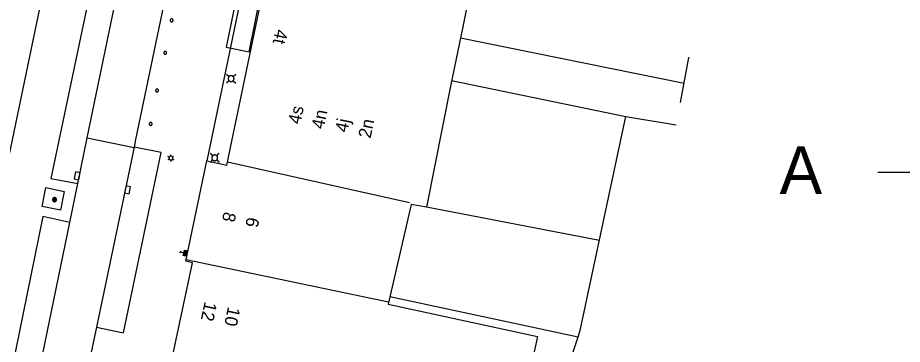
# Model space of a CAD drawing. Extents: x 81065 to 81486, y 452384 to 452681.
# Drawn here: x 81276.3 to 81331.8, y 452560.2 to 452580.7 of the extents above; entities that cross this region are included whole.
import ezdxf

# ---------------------------------------------------------------- set-up
doc = ezdxf.new("R2010")
doc.units = 0
for name, color, linetype in [('B-BH-AL-TOPOGRAFIE_HUISNUMMER-T25', 7, 'Continuous'), ('B-BH-GR-BOOM-S', 7, 'Continuous'), ('B-BH-IE-MEUBILAIR_WEGMEUBILAIR_LICHTMAST-S', 7, 'Continuous'), ('B-BH-IE-MEUBILAIR_WEGMEUBILAIR_PAAL-S', 7, 'Continuous'), ('B-BH-KL-DATA_CAI_KAST-S', 7, 'Continuous'), ('B-BH-OG-TERREIN_ERF-GV', 7, 'Continuous'), ('B-BH-OG-TOPOGRAFIE_BEBOUWING-GV', 7, 'Continuous'), ('B-BH-OG-TOPOGRAFIE_BEBOUWING_PANDSCHEIDING-GV', 7, 'Continuous'), ('B-BH-VH-KANTOPSLUITING-GV', 7, 'Continuous'), ('B-SRI-KOLK_COMBINATIE-S', 7, 'Continuous'), ('X-XX-AL-TEKENBLAD_KADER-G', 7, 'Continuous')]:
    doc.layers.add(name, color=color, linetype=linetype)

msp = doc.modelspace()

# ---------------------------------------------------------------- linework, layer by layer
at = {"layer": 'B-BH-GR-BOOM-S'}
for points in [[(81278.456, 452569.271), (81278.457, 452569.257), (81278.459, 452569.244), (81278.462, 452569.231), (81278.467, 452569.219), (81278.473, 452569.207), (81278.481, 452569.195), (81278.489, 452569.185), (81278.499, 452569.175), (81278.509, 452569.167), (81278.521, 452569.159), (81278.533, 452569.153), (81278.545, 452569.148), (81278.558, 452569.145), (81278.571, 452569.143), (81278.585, 452569.142), (81278.598, 452569.143), (81278.612, 452569.145), (81278.625, 452569.148), (81278.637, 452569.153), (81278.649, 452569.159), (81278.661, 452569.167), (81278.671, 452569.175), (81278.681, 452569.185), (81278.689, 452569.195), (81278.697, 452569.207), (81278.703, 452569.219), (81278.707, 452569.231), (81278.711, 452569.244), (81278.713, 452569.257), (81278.714, 452569.271), (81278.713, 452569.284), (81278.711, 452569.298), (81278.707, 452569.311), (81278.703, 452569.323), (81278.697, 452569.335), (81278.689, 452569.347), (81278.681, 452569.357), (81278.671, 452569.367), (81278.661, 452569.375), (81278.649, 452569.383), (81278.637, 452569.389), (81278.625, 452569.393), (81278.612, 452569.397), (81278.598, 452569.399), (81278.585, 452569.4), (81278.571, 452569.399), (81278.558, 452569.397), (81278.545, 452569.393), (81278.533, 452569.389), (81278.521, 452569.383), (81278.509, 452569.375), (81278.499, 452569.367), (81278.489, 452569.357), (81278.481, 452569.347), (81278.473, 452569.335), (81278.467, 452569.323), (81278.462, 452569.311), (81278.459, 452569.298), (81278.457, 452569.284), (81278.456, 452569.271)], [(81278.481, 452569.271), (81278.481, 452569.26), (81278.483, 452569.249), (81278.486, 452569.239), (81278.49, 452569.228), (81278.494, 452569.219), (81278.5, 452569.21), (81278.507, 452569.201), (81278.515, 452569.193), (81278.524, 452569.186), (81278.533, 452569.18), (81278.542, 452569.176), (81278.553, 452569.172), (81278.563, 452569.169), (81278.574, 452569.167), (81278.585, 452569.167), (81278.596, 452569.167), (81278.607, 452569.169), (81278.617, 452569.172), (81278.627, 452569.176), (81278.637, 452569.18), (81278.646, 452569.186), (81278.655, 452569.193), (81278.663, 452569.201), (81278.669, 452569.21), (81278.675, 452569.219), (81278.68, 452569.228), (81278.684, 452569.239), (81278.687, 452569.249), (81278.689, 452569.26), (81278.689, 452569.271), (81278.689, 452569.282), (81278.687, 452569.293), (81278.684, 452569.303), (81278.68, 452569.313), (81278.675, 452569.323), (81278.669, 452569.332), (81278.663, 452569.341), (81278.655, 452569.349), (81278.646, 452569.355), (81278.637, 452569.361), (81278.627, 452569.366), (81278.617, 452569.37), (81278.607, 452569.373), (81278.596, 452569.375), (81278.585, 452569.375), (81278.574, 452569.375), (81278.563, 452569.373), (81278.553, 452569.37), (81278.542, 452569.366), (81278.533, 452569.361), (81278.524, 452569.355), (81278.515, 452569.349), (81278.507, 452569.341), (81278.5, 452569.332), (81278.494, 452569.323), (81278.49, 452569.313), (81278.486, 452569.303), (81278.483, 452569.293), (81278.481, 452569.282), (81278.481, 452569.271)], [(81278.503, 452569.271), (81278.504, 452569.262), (81278.505, 452569.254), (81278.507, 452569.246), (81278.51, 452569.238), (81278.514, 452569.23), (81278.519, 452569.223), (81278.524, 452569.216), (81278.53, 452569.21), (81278.537, 452569.205), (81278.544, 452569.2), (81278.552, 452569.196), (81278.56, 452569.193), (81278.568, 452569.191), (81278.576, 452569.19), (81278.585, 452569.189), (81278.593, 452569.19), (81278.602, 452569.191), (81278.61, 452569.193), (81278.618, 452569.196), (81278.626, 452569.2), (81278.633, 452569.205), (81278.64, 452569.21), (81278.646, 452569.216), (81278.651, 452569.223), (81278.656, 452569.23), (81278.659, 452569.238), (81278.663, 452569.246), (81278.665, 452569.254), (81278.666, 452569.262), (81278.667, 452569.271), (81278.666, 452569.279), (81278.665, 452569.288), (81278.663, 452569.296), (81278.659, 452569.304), (81278.656, 452569.312), (81278.651, 452569.319), (81278.646, 452569.326), (81278.64, 452569.332), (81278.633, 452569.337), (81278.626, 452569.342), (81278.618, 452569.345), (81278.61, 452569.349), (81278.602, 452569.351), (81278.593, 452569.352), (81278.585, 452569.353), (81278.576, 452569.352), (81278.568, 452569.351), (81278.56, 452569.349), (81278.552, 452569.345), (81278.544, 452569.342), (81278.537, 452569.337), (81278.53, 452569.332), (81278.524, 452569.326), (81278.519, 452569.319), (81278.514, 452569.312), (81278.51, 452569.304), (81278.507, 452569.296), (81278.505, 452569.288), (81278.504, 452569.279), (81278.503, 452569.271)], [(81278.526, 452569.271), (81278.527, 452569.265), (81278.528, 452569.259), (81278.529, 452569.253), (81278.531, 452569.247), (81278.534, 452569.242), (81278.538, 452569.236), (81278.541, 452569.232), (81278.546, 452569.227), (81278.55, 452569.224), (81278.556, 452569.22), (81278.561, 452569.217), (81278.567, 452569.215), (81278.573, 452569.214), (81278.579, 452569.213), (81278.585, 452569.212), (81278.591, 452569.213), (81278.597, 452569.214), (81278.603, 452569.215), (81278.609, 452569.217), (81278.614, 452569.22), (81278.619, 452569.224), (81278.624, 452569.227), (81278.629, 452569.232), (81278.632, 452569.236), (81278.636, 452569.242), (81278.639, 452569.247), (81278.641, 452569.253), (81278.642, 452569.259), (81278.643, 452569.265), (81278.644, 452569.271), (81278.643, 452569.277), (81278.642, 452569.283), (81278.641, 452569.289), (81278.639, 452569.295), (81278.636, 452569.3), (81278.632, 452569.305), (81278.629, 452569.31), (81278.624, 452569.315), (81278.619, 452569.318), (81278.614, 452569.322), (81278.609, 452569.325), (81278.603, 452569.327), (81278.597, 452569.328), (81278.591, 452569.329), (81278.585, 452569.33), (81278.579, 452569.329), (81278.573, 452569.328), (81278.567, 452569.327), (81278.561, 452569.325), (81278.556, 452569.322), (81278.55, 452569.318), (81278.546, 452569.315), (81278.541, 452569.31), (81278.538, 452569.305), (81278.534, 452569.3), (81278.531, 452569.295), (81278.529, 452569.289), (81278.528, 452569.283), (81278.527, 452569.277), (81278.526, 452569.271)], [(81278.549, 452569.271), (81278.549, 452569.267), (81278.55, 452569.264), (81278.551, 452569.26), (81278.552, 452569.256), (81278.554, 452569.253), (81278.556, 452569.25), (81278.558, 452569.247), (81278.561, 452569.244), (81278.564, 452569.242), (81278.567, 452569.24), (81278.57, 452569.238), (81278.574, 452569.237), (81278.578, 452569.236), (81278.581, 452569.235), (81278.585, 452569.235), (81278.589, 452569.235), (81278.592, 452569.236), (81278.596, 452569.237), (81278.6, 452569.238), (81278.603, 452569.24), (81278.606, 452569.242), (81278.609, 452569.244), (81278.611, 452569.247), (81278.614, 452569.25), (81278.616, 452569.253), (81278.618, 452569.256), (81278.619, 452569.26), (81278.62, 452569.264), (81278.621, 452569.267), (81278.621, 452569.271), (81278.621, 452569.275), (81278.62, 452569.278), (81278.619, 452569.282), (81278.618, 452569.286), (81278.616, 452569.289), (81278.614, 452569.292), (81278.611, 452569.295), (81278.609, 452569.297), (81278.606, 452569.3), (81278.603, 452569.302), (81278.6, 452569.304), (81278.596, 452569.305), (81278.592, 452569.306), (81278.589, 452569.307), (81278.585, 452569.307), (81278.581, 452569.307), (81278.578, 452569.306), (81278.574, 452569.305), (81278.57, 452569.304), (81278.567, 452569.302), (81278.564, 452569.3), (81278.561, 452569.297), (81278.558, 452569.295), (81278.556, 452569.292), (81278.554, 452569.289), (81278.552, 452569.286), (81278.551, 452569.282), (81278.55, 452569.278), (81278.549, 452569.275), (81278.549, 452569.271)], [(81278.572, 452569.271), (81278.572, 452569.27), (81278.572, 452569.268), (81278.573, 452569.267), (81278.573, 452569.266), (81278.574, 452569.265), (81278.575, 452569.263), (81278.575, 452569.262), (81278.576, 452569.261), (81278.577, 452569.261), (81278.579, 452569.26), (81278.58, 452569.259), (81278.581, 452569.259), (81278.582, 452569.258), (81278.584, 452569.258), (81278.585, 452569.258), (81278.586, 452569.258), (81278.588, 452569.258), (81278.589, 452569.259), (81278.59, 452569.259), (81278.591, 452569.26), (81278.593, 452569.261), (81278.594, 452569.261), (81278.595, 452569.262), (81278.595, 452569.263), (81278.596, 452569.265), (81278.597, 452569.266), (81278.597, 452569.267), (81278.598, 452569.268), (81278.598, 452569.27), (81278.598, 452569.271), (81278.598, 452569.272), (81278.598, 452569.274), (81278.597, 452569.275), (81278.597, 452569.276), (81278.596, 452569.277), (81278.595, 452569.279), (81278.595, 452569.28), (81278.594, 452569.281), (81278.593, 452569.281), (81278.591, 452569.282), (81278.59, 452569.283), (81278.589, 452569.283), (81278.588, 452569.284), (81278.586, 452569.284), (81278.585, 452569.284), (81278.584, 452569.284), (81278.582, 452569.284), (81278.581, 452569.283), (81278.58, 452569.283), (81278.579, 452569.282), (81278.577, 452569.281), (81278.576, 452569.281), (81278.575, 452569.28), (81278.575, 452569.279), (81278.574, 452569.277), (81278.573, 452569.276), (81278.573, 452569.275), (81278.572, 452569.274), (81278.572, 452569.272), (81278.572, 452569.271)]]:
    msp.add_lwpolyline(points, dxfattribs=at)
at = {"layer": 'B-BH-IE-MEUBILAIR_WEGMEUBILAIR_LICHTMAST-S'}
for p, q in [((81285.787, 452571.941), (81285.708, 452571.987)), ((81285.787, 452571.819), (81285.708, 452571.773)), ((81285.893, 452572.002), (81285.893, 452572.094)), ((81285.998, 452571.941), (81286.078, 452571.987)), ((81285.998, 452571.819), (81286.078, 452571.773)), ((81285.893, 452571.758), (81285.893, 452571.666))]:
    msp.add_line(p, q, dxfattribs=at)
msp.add_lwpolyline([(81285.771, 452571.88), (81285.772, 452571.867), (81285.773, 452571.854), (81285.777, 452571.842), (81285.781, 452571.83), (81285.787, 452571.819), (81285.794, 452571.808), (81285.802, 452571.798), (81285.811, 452571.789), (81285.821, 452571.781), (81285.832, 452571.774), (81285.843, 452571.768), (81285.855, 452571.764), (81285.868, 452571.76), (81285.88, 452571.759), (81285.893, 452571.758), (81285.906, 452571.759), (81285.918, 452571.76), (81285.931, 452571.764), (81285.943, 452571.768), (81285.954, 452571.774), (81285.965, 452571.781), (81285.975, 452571.789), (81285.984, 452571.798), (81285.992, 452571.808), (81285.999, 452571.819), (81286.004, 452571.83), (81286.009, 452571.842), (81286.012, 452571.854), (81286.014, 452571.867), (81286.015, 452571.88), (81286.014, 452571.893), (81286.012, 452571.905), (81286.009, 452571.918), (81286.004, 452571.93), (81285.999, 452571.941), (81285.992, 452571.952), (81285.984, 452571.962), (81285.975, 452571.971), (81285.965, 452571.979), (81285.954, 452571.986), (81285.943, 452571.991), (81285.931, 452571.996), (81285.918, 452571.999), (81285.906, 452572.001), (81285.893, 452572.002), (81285.88, 452572.001), (81285.867, 452571.999), (81285.855, 452571.996), (81285.843, 452571.991), (81285.832, 452571.986), (81285.821, 452571.979), (81285.811, 452571.971), (81285.802, 452571.962), (81285.794, 452571.952), (81285.787, 452571.941), (81285.781, 452571.93), (81285.777, 452571.918), (81285.773, 452571.905), (81285.772, 452571.893), (81285.771, 452571.88)], dxfattribs=at)
at = {"layer": 'B-BH-IE-MEUBILAIR_WEGMEUBILAIR_PAAL-S'}
for points in [[(81285.846, 452580.529), (81285.847, 452580.519), (81285.848, 452580.51), (81285.851, 452580.5), (81285.854, 452580.491), (81285.858, 452580.483), (81285.864, 452580.475), (81285.87, 452580.467), (81285.876, 452580.461), (81285.884, 452580.455), (81285.892, 452580.449), (81285.901, 452580.445), (81285.909, 452580.442), (81285.919, 452580.439), (81285.928, 452580.438), (81285.938, 452580.437), (81285.947, 452580.438), (81285.957, 452580.439), (81285.966, 452580.442), (81285.975, 452580.445), (81285.984, 452580.449), (81285.992, 452580.455), (81285.999, 452580.461), (81286.006, 452580.467), (81286.012, 452580.475), (81286.017, 452580.483), (81286.021, 452580.491), (81286.025, 452580.5), (81286.027, 452580.51), (81286.029, 452580.519), (81286.029, 452580.529), (81286.029, 452580.538), (81286.027, 452580.548), (81286.025, 452580.557), (81286.021, 452580.566), (81286.017, 452580.574), (81286.012, 452580.582), (81286.006, 452580.59), (81285.999, 452580.597), (81285.992, 452580.603), (81285.984, 452580.608), (81285.975, 452580.612), (81285.966, 452580.616), (81285.957, 452580.618), (81285.947, 452580.62), (81285.938, 452580.62), (81285.928, 452580.62), (81285.919, 452580.618), (81285.909, 452580.616), (81285.901, 452580.612), (81285.892, 452580.608), (81285.884, 452580.603), (81285.876, 452580.597), (81285.87, 452580.59), (81285.864, 452580.582), (81285.858, 452580.574), (81285.854, 452580.566), (81285.851, 452580.557), (81285.848, 452580.548), (81285.847, 452580.538), (81285.846, 452580.529)], [(81285.442, 452578.492), (81285.443, 452578.482), (81285.444, 452578.473), (81285.447, 452578.463), (81285.45, 452578.454), (81285.454, 452578.446), (81285.46, 452578.438), (81285.466, 452578.43), (81285.472, 452578.424), (81285.48, 452578.418), (81285.488, 452578.412), (81285.497, 452578.408), (81285.505, 452578.405), (81285.515, 452578.402), (81285.524, 452578.401), (81285.534, 452578.4), (81285.543, 452578.401), (81285.553, 452578.402), (81285.562, 452578.405), (81285.571, 452578.408), (81285.58, 452578.412), (81285.588, 452578.418), (81285.595, 452578.424), (81285.602, 452578.43), (81285.608, 452578.438), (81285.613, 452578.446), (81285.617, 452578.454), (81285.621, 452578.463), (81285.623, 452578.473), (81285.625, 452578.482), (81285.625, 452578.492), (81285.625, 452578.501), (81285.623, 452578.511), (81285.621, 452578.52), (81285.617, 452578.529), (81285.613, 452578.537), (81285.608, 452578.545), (81285.602, 452578.553), (81285.595, 452578.56), (81285.588, 452578.566), (81285.58, 452578.571), (81285.571, 452578.575), (81285.562, 452578.579), (81285.553, 452578.581), (81285.543, 452578.583), (81285.534, 452578.583), (81285.524, 452578.583), (81285.515, 452578.581), (81285.505, 452578.579), (81285.497, 452578.575), (81285.488, 452578.571), (81285.48, 452578.566), (81285.472, 452578.56), (81285.466, 452578.553), (81285.46, 452578.545), (81285.454, 452578.537), (81285.45, 452578.529), (81285.447, 452578.52), (81285.444, 452578.511), (81285.443, 452578.501), (81285.442, 452578.492)], [(81284.931, 452576.122), (81284.932, 452576.112), (81284.933, 452576.103), (81284.936, 452576.093), (81284.939, 452576.084), (81284.943, 452576.076), (81284.949, 452576.068), (81284.955, 452576.06), (81284.961, 452576.054), (81284.969, 452576.048), (81284.977, 452576.042), (81284.986, 452576.038), (81284.994, 452576.035), (81285.004, 452576.032), (81285.013, 452576.031), (81285.023, 452576.03), (81285.032, 452576.031), (81285.042, 452576.032), (81285.051, 452576.035), (81285.06, 452576.038), (81285.069, 452576.042), (81285.077, 452576.048), (81285.084, 452576.054), (81285.091, 452576.06), (81285.097, 452576.068), (81285.102, 452576.076), (81285.106, 452576.084), (81285.11, 452576.093), (81285.112, 452576.103), (81285.114, 452576.112), (81285.114, 452576.122), (81285.114, 452576.131), (81285.112, 452576.141), (81285.11, 452576.15), (81285.106, 452576.159), (81285.102, 452576.167), (81285.097, 452576.175), (81285.091, 452576.183), (81285.084, 452576.19), (81285.077, 452576.196), (81285.069, 452576.201), (81285.06, 452576.205), (81285.051, 452576.209), (81285.042, 452576.211), (81285.032, 452576.213), (81285.023, 452576.213), (81285.013, 452576.213), (81285.004, 452576.211), (81284.994, 452576.209), (81284.986, 452576.205), (81284.977, 452576.201), (81284.969, 452576.196), (81284.961, 452576.19), (81284.955, 452576.183), (81284.949, 452576.175), (81284.943, 452576.167), (81284.939, 452576.159), (81284.936, 452576.15), (81284.933, 452576.141), (81284.932, 452576.131), (81284.931, 452576.122)], [(81284.532, 452574.027), (81284.533, 452574.017), (81284.534, 452574.008), (81284.537, 452573.998), (81284.54, 452573.989), (81284.544, 452573.981), (81284.55, 452573.973), (81284.556, 452573.965), (81284.562, 452573.959), (81284.57, 452573.953), (81284.578, 452573.947), (81284.587, 452573.943), (81284.595, 452573.94), (81284.605, 452573.937), (81284.614, 452573.936), (81284.624, 452573.935), (81284.633, 452573.936), (81284.643, 452573.937), (81284.652, 452573.94), (81284.661, 452573.943), (81284.67, 452573.947), (81284.678, 452573.953), (81284.685, 452573.959), (81284.692, 452573.965), (81284.698, 452573.973), (81284.703, 452573.981), (81284.707, 452573.989), (81284.711, 452573.998), (81284.713, 452574.008), (81284.715, 452574.017), (81284.715, 452574.027), (81284.715, 452574.036), (81284.713, 452574.046), (81284.711, 452574.055), (81284.707, 452574.064), (81284.703, 452574.072), (81284.698, 452574.08), (81284.692, 452574.088), (81284.685, 452574.095), (81284.678, 452574.101), (81284.67, 452574.106), (81284.661, 452574.11), (81284.652, 452574.114), (81284.643, 452574.116), (81284.633, 452574.118), (81284.624, 452574.118), (81284.614, 452574.118), (81284.605, 452574.116), (81284.595, 452574.114), (81284.587, 452574.11), (81284.578, 452574.106), (81284.57, 452574.101), (81284.562, 452574.095), (81284.556, 452574.088), (81284.55, 452574.08), (81284.544, 452574.072), (81284.54, 452574.064), (81284.537, 452574.055), (81284.534, 452574.046), (81284.533, 452574.036), (81284.532, 452574.027)]]:
    msp.add_lwpolyline(points, dxfattribs=at)
at = {"layer": 'B-BH-KL-DATA_CAI_KAST-S'}
for p, q in [((81286.474, 452565.925), (81286.508, 452566.058)), ((81286.492, 452565.992), (81286.711, 452565.936)), ((81286.668, 452565.766), (81286.755, 452566.106)), ((81286.813, 452565.73), (81286.668, 452565.766)), ((81286.697, 452565.778), (81286.774, 452566.082)), ((81286.793, 452565.754), (81286.697, 452565.778)), ((81286.726, 452565.79), (81286.794, 452566.059)), ((81286.774, 452565.778), (81286.726, 452565.79)), ((81286.754, 452565.802), (81286.813, 452566.035)), ((81286.755, 452566.106), (81286.899, 452566.07)), ((81286.774, 452566.082), (81286.87, 452566.058)), ((81286.774, 452565.778), (81286.842, 452566.046)), ((81286.793, 452565.754), (81286.87, 452566.058)), ((81286.794, 452566.059), (81286.842, 452566.046)), ((81286.899, 452566.07), (81286.813, 452565.73))]:
    msp.add_line(p, q, dxfattribs=at)
at = {"layer": 'B-BH-OG-TERREIN_ERF-GV'}
for p, q in [((81312.803, 452566.708), (81301.952, 452568.801)), ((81299.645, 452563.184), (81311.462, 452560.651))]:
    msp.add_line(p, q, dxfattribs=at)
at = {"layer": 'B-BH-OG-TOPOGRAFIE_BEBOUWING-GV'}
for p, q in [((81291.963, 452590.077), (81288.147, 452571.707)), ((81290.811, 452578.546), (81292.979, 452589.322)), ((81318.116, 452576.566), (81304.084, 452579.412)), ((81289.389, 452577.156), (81289.545, 452576.999)), ((81289.804, 452576.999), (81289.961, 452577.156)), ((81289.545, 452576.74), (81289.389, 452576.584)), ((81289.804, 452576.74), (81289.961, 452576.584)), ((81303.524, 452576.752), (81314.468, 452574.499)), ((81288.357, 452572.181), (81288.513, 452572.024)), ((81288.772, 452572.024), (81288.929, 452572.181)), ((81288.513, 452571.765), (81288.357, 452571.609)), ((81288.772, 452571.765), (81288.929, 452571.609))]:
    msp.add_line(p, q, dxfattribs=at)
for points in [[(81286.276, 452538.555), (81285.609, 452539.778), (81285.995, 452539.989), (81283.022, 452545.459), (81287.25, 452565.297), (81286.821, 452565.397), (81288.147, 452571.707), (81289.4, 452571.444), (81292.656, 452587.012), (81292.95, 452586.951), (81293.53, 452589.752), (81291.963, 452590.077), (81296.676, 452612.828), (81299.951, 452612.1), (81301.047, 452613.797), (81298.997, 452616.496), (81301.21, 452618.158)], [(81292.979, 452589.322), (81291.571, 452589.579), (81289.361, 452578.844), (81290.811, 452578.546)], [(81305.05, 452584.196), (81304.256, 452580.227), (81303.447, 452576.388)], [(81317.896, 452575.366), (81318.415, 452578.196), (81318.455, 452578.188)], [(81289.492, 452576.87), (81289.493, 452576.851), (81289.496, 452576.832), (81289.501, 452576.813), (81289.508, 452576.795), (81289.516, 452576.778), (81289.527, 452576.762), (81289.539, 452576.747), (81289.552, 452576.734), (81289.567, 452576.722), (81289.583, 452576.711), (81289.6, 452576.703), (81289.618, 452576.696), (81289.637, 452576.691), (81289.656, 452576.688), (81289.675, 452576.687), (81289.694, 452576.688), (81289.713, 452576.691), (81289.732, 452576.696), (81289.749, 452576.703), (81289.766, 452576.711), (81289.783, 452576.722), (81289.797, 452576.734), (81289.811, 452576.747), (81289.823, 452576.762), (81289.833, 452576.778), (81289.842, 452576.795), (81289.849, 452576.813), (81289.854, 452576.832), (81289.857, 452576.851), (81289.858, 452576.87), (81289.857, 452576.889), (81289.854, 452576.908), (81289.849, 452576.927), (81289.842, 452576.944), (81289.833, 452576.961), (81289.823, 452576.978), (81289.811, 452576.992), (81289.797, 452577.006), (81289.783, 452577.018), (81289.766, 452577.028), (81289.749, 452577.037), (81289.732, 452577.044), (81289.713, 452577.049), (81289.694, 452577.052), (81289.675, 452577.053), (81289.656, 452577.052), (81289.637, 452577.049), (81289.618, 452577.044), (81289.6, 452577.037), (81289.583, 452577.028), (81289.567, 452577.018), (81289.552, 452577.006), (81289.539, 452576.992), (81289.527, 452576.978), (81289.516, 452576.961), (81289.508, 452576.944), (81289.501, 452576.927), (81289.496, 452576.908), (81289.493, 452576.889), (81289.492, 452576.87)], [(81303.447, 452576.388), (81301.952, 452568.801), (81300.972, 452568.964), (81299.536, 452562.709), (81308.918, 452560.67), (81307.949, 452556.209), (81305.471, 452556.748), (81305.345, 452556.166), (81298.463, 452557.662), (81298.378, 452557.26), (81309.143, 452555.074), (81309.231, 452555.26), (81309.665, 452555.195), (81311.462, 452560.651), (81311.594, 452561.05), (81314.468, 452574.499), (81317.618, 452573.966)], [(81288.46, 452571.895), (81288.461, 452571.876), (81288.464, 452571.857), (81288.469, 452571.838), (81288.476, 452571.82), (81288.484, 452571.803), (81288.495, 452571.787), (81288.507, 452571.772), (81288.52, 452571.759), (81288.535, 452571.747), (81288.551, 452571.736), (81288.568, 452571.728), (81288.586, 452571.721), (81288.605, 452571.716), (81288.624, 452571.713), (81288.643, 452571.712), (81288.662, 452571.713), (81288.681, 452571.716), (81288.7, 452571.721), (81288.717, 452571.728), (81288.734, 452571.736), (81288.751, 452571.747), (81288.765, 452571.759), (81288.779, 452571.772), (81288.791, 452571.787), (81288.801, 452571.803), (81288.81, 452571.82), (81288.817, 452571.838), (81288.822, 452571.857), (81288.825, 452571.876), (81288.826, 452571.895), (81288.825, 452571.914), (81288.822, 452571.933), (81288.817, 452571.952), (81288.81, 452571.969), (81288.801, 452571.986), (81288.791, 452572.003), (81288.779, 452572.017), (81288.765, 452572.031), (81288.751, 452572.043), (81288.734, 452572.053), (81288.717, 452572.062), (81288.7, 452572.069), (81288.681, 452572.074), (81288.662, 452572.077), (81288.643, 452572.078), (81288.624, 452572.077), (81288.605, 452572.074), (81288.586, 452572.069), (81288.568, 452572.062), (81288.551, 452572.053), (81288.535, 452572.043), (81288.52, 452572.031), (81288.507, 452572.017), (81288.495, 452572.003), (81288.484, 452571.986), (81288.476, 452571.969), (81288.469, 452571.952), (81288.464, 452571.933), (81288.461, 452571.914), (81288.46, 452571.895)]]:
    msp.add_lwpolyline(points, dxfattribs=at)
at = {"layer": 'B-BH-OG-TOPOGRAFIE_BEBOUWING_PANDSCHEIDING-GV'}
for p, q in [((81300.886, 452569.07), (81289.437, 452571.622)), ((81286.847, 452565.521), (81299.566, 452562.855))]:
    msp.add_line(p, q, dxfattribs=at)
at = {"layer": 'B-BH-VH-KANTOPSLUITING-GV'}
for p, q in [((81280.642, 452573.147), (81283.576, 452572.555)), ((81283.578, 452572.566), (81281.224, 452561.267)), ((81279.537, 452567.844), (81280.051, 452570.287)), ((81276.314, 452552.171), (81279.537, 452567.844)), ((81281.224, 452561.267), (81280.167, 452556.385))]:
    msp.add_line(p, q, dxfattribs=at)
for points in [[(81267.731, 452533.684), (81282.916, 452606.564), (81283.089, 452607.976)], [(81283.382, 452586.39), (81281.735, 452586.735), (81278.353, 452570.592), (81280.051, 452570.287)], [(81280.051, 452570.287), (81280.642, 452573.147), (81283.382, 452586.39)], [(81285.598, 452582.374), (81285.508, 452581.891), (81283.673, 452573.048), (81283.578, 452572.566)], [(81281.224, 452561.267), (81282.911, 452560.907), (81285.273, 452572.224), (81283.578, 452572.566)], [(81278.039, 452570.03), (81279.192, 452569.791), (81278.96, 452568.61), (81277.807, 452568.849), (81278.039, 452570.03)], [(81279.537, 452567.844), (81277.84, 452568.205), (81274.621, 452552.477), (81276.314, 452552.171)]]:
    msp.add_lwpolyline(points, dxfattribs=at)
at = {"layer": 'B-SRI-KOLK_COMBINATIE-S'}
for p, q in [((81279.903, 452571.018), (81279.814, 452570.579)), ((81280.193, 452570.959), (81279.903, 452571.018)), ((81280.103, 452570.52), (81280.193, 452570.959)), ((81279.814, 452570.579), (81280.103, 452570.52)), ((81283.073, 452570.139), (81282.981, 452569.7)), ((81283.362, 452570.078), (81283.073, 452570.139)), ((81282.981, 452569.7), (81283.27, 452569.64)), ((81283.27, 452569.64), (81283.362, 452570.078))]:
    msp.add_line(p, q, dxfattribs=at)
at = {"layer": 'X-XX-AL-TEKENBLAD_KADER-G'}
msp.add_line((81330.293, 452570.997), (81405.616, 452570.997), dxfattribs=at)

# ---------------------------------------------------------------- texts
at = {"layer": 'B-BH-AL-TOPOGRAFIE_HUISNUMMER-T25'}
for s, rotation, p in [('4t', 258.187, (81292.469, 452580.007)), ('4s', 78.3983, (81294.019, 452573.968)), ('4n', 78.3983, (81295.488, 452573.666)), ('4j', 78.3983, (81296.976, 452573.458)), ('2n', 78.3983, (81298.43, 452573.082)), ('8', 257.9688, (81289.221, 452568.547)), ('6', 257.9688, (81290.684, 452568.216)), ('12', 257.9688, (81288.017, 452562.9)), ('10', 257.9688, (81289.484, 452562.584))]:
    msp.add_text(s, height=0.8, rotation=rotation, dxfattribs=at).set_placement(p)
at = {"layer": 'X-XX-AL-TEKENBLAD_KADER-G'}
msp.add_text('A', height=3, rotation=0.1528, dxfattribs=at).set_placement((81324.116, 452569.619))

doc.saveas('drawing.dxf')
